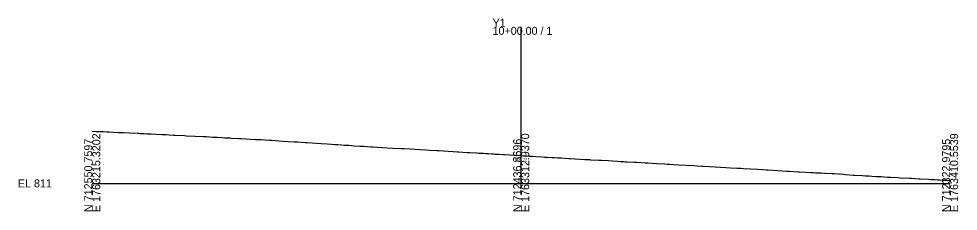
# Model space of a CAD drawing. Extents: x -26 to 1303, y -10 to 9524.
# Drawn here: x -25.7 to 302.8, y -9.7 to 57.5 of the extents above; entities that cross this region are included whole.
import ezdxf

# ---------------------------------------------------------------- set-up
doc = ezdxf.new("R2010")
doc.units = 0
for name, color, linetype in [('Default', 7, 'Continuous'), ('Exist Cross Section Cell', 7, 'Continuous'), ('Exist XS Center Line Elevation Label', 7, 'Continuous'), ('Exist XS Ground Line', 7, 'Continuous')]:
    doc.layers.add(name, color=color, linetype=linetype)

msp = doc.modelspace()

# ---------------------------------------------------------------- linework, layer by layer
at = {"layer": 'Exist Cross Section Cell'}
for p, q in [((150, 0), (150, 54.67)), ((0, 0), (150, 0)), ((150, 0), (300, 0))]:
    msp.add_line(p, q, dxfattribs=at)
at = {"layer": 'Exist XS Ground Line'}
msp.add_lwpolyline([(0, 18.22), (1.43, 18.18), (2.08, 18.16), (2.65, 18.14), (3.86, 18.08), (5.27, 18.01), (5.63, 18), (5.94, 17.99), (7.4, 17.92), (9.23, 17.82), (10.95, 17.75), (12.95, 17.66), (15.82, 17.53), (16.27, 17.51), (16.79, 17.48), (18.04, 17.41), (19.11, 17.35), (20.64, 17.28), (22.4, 17.19), (24.48, 17.09), (25.7, 17.03), (26.91, 16.97), (28.32, 16.9), (28.68, 16.88), (28.99, 16.86), (32.28, 16.7), (33, 16.66), (36, 16.52), (38.87, 16.39), (39.84, 16.33), (42.16, 16.2), (43.69, 16.1), (45.45, 16), (46.41, 15.96), (47.53, 15.9), (48.18, 15.86), (48.74, 15.84), (51.37, 15.7), (52.04, 15.66), (55.33, 15.46), (57.05, 15.38), (58.62, 15.3), (59.05, 15.28), (61.91, 15.12), (62.37, 15.08), (62.89, 15.06), (65.21, 14.92), (66.74, 14.8), (68.5, 14.68), (70.58, 14.57), (71.23, 14.53), (71.79, 14.5), (74.42, 14.31), (75.09, 14.26), (78.38, 14.02), (80.1, 13.9), (82.1, 13.8), (83.64, 13.7), (84.96, 13.6), (85.42, 13.57), (85.94, 13.54), (87.19, 13.46), (88.26, 13.4), (88.96, 13.36), (89.78, 13.3), (91.55, 13.17), (93.63, 13.04), (94.28, 13), (94.84, 12.97), (97.47, 12.81), (97.83, 12.78), (98.13, 12.76), (99.6, 12.69), (101.43, 12.56), (103.15, 12.48), (105.15, 12.34), (108.01, 12.2), (108.99, 12.14), (111.3, 12.02), (112.83, 11.94), (114.6, 11.85), (116.68, 11.73), (117.89, 11.66), (120.52, 11.5), (121.18, 11.46), (124.47, 11.26), (126.19, 11.17), (127.77, 11.06), (128.2, 11.03), (131.06, 10.85), (132.04, 10.79), (134.35, 10.65), (135.06, 10.61), (135.88, 10.56), (136.83, 10.52), (137.65, 10.46), (138.61, 10.4), (139.72, 10.32), (140.38, 10.28), (140.94, 10.26), (142.15, 10.21), (143.57, 10.11), (144.23, 10.06), (147.52, 9.87), (148.22, 9.83), (150, 9.72), (151.25, 9.64), (152.79, 9.56), (154.11, 9.47), (155.09, 9.41), (157.4, 9.25), (158.11, 9.2), (158.93, 9.15), (160.69, 9.07), (161.65, 9.02), (162.77, 8.94), (163.43, 8.91), (163.99, 8.88), (166.62, 8.73), (167.28, 8.68), (170.57, 8.5), (172.29, 8.39), (173.86, 8.31), (174.3, 8.29), (177.16, 8.12), (178.14, 8.08), (180.45, 7.95), (181.98, 7.87), (183.74, 7.76), (184.7, 7.7), (185.82, 7.63), (186.42, 7.59), (187.04, 7.56), (189.66, 7.42), (190.33, 7.38), (193.51, 7.18), (193.86, 7.15), (194.31, 7.13), (197.35, 6.96), (200.21, 6.79), (201.19, 6.74), (202.02, 6.7), (203.5, 6.61), (205.03, 6.53), (210.41, 6.23), (211.49, 6.17), (213.21, 6.08), (213.78, 6.04), (215.98, 5.92), (221.55, 5.59), (223.25, 5.49), (225.38, 5.36), (226.52, 5.29), (226.87, 5.27), (227.79, 5.23), (232.66, 4.97), (234.38, 4.85), (235.76, 4.77), (236.42, 4.73), (239.72, 4.55), (241.14, 4.42), (242.91, 4.32), (243.61, 4.28), (246.84, 4.08), (247.29, 4.06), (249.6, 3.94), (251.13, 3.84), (252.08, 3.79), (252.89, 3.75), (254.97, 3.65), (256.18, 3.58), (258.81, 3.45), (259.47, 3.42), (260.94, 3.32), (262.77, 3.18), (263.44, 3.12), (266.06, 2.9), (266.5, 2.87), (269.35, 2.72), (270.34, 2.68), (271.58, 2.62), (272.64, 2.55), (274.18, 2.46), (275.94, 2.36), (278.02, 2.23), (279.23, 2.16), (281.86, 2.03), (282.52, 1.99), (285.81, 1.83), (286.48, 1.79), (289.11, 1.63), (289.55, 1.61), (292.4, 1.44), (293.39, 1.39), (294.63, 1.33), (295.69, 1.27), (296.4, 1.24), (297.23, 1.19), (298.17, 1.14), (298.99, 1.09), (300, 1.03)], dxfattribs=at)

# ---------------------------------------------------------------- texts
at = {"layer": 'Default'}
msp.add_text('-', height=0.0001, dxfattribs=at).set_placement((0, 0))
at = {"layer": 'Exist Cross Section Cell'}
for s, p in [('Y1', (140, 54.67)), ('10+00.00 / 1', (140, 51.87)), ('EL 811', (-26, -1.4))]:
    msp.add_text(s, height=2.8, dxfattribs=at).set_placement(p)
for s, p in [('E 1763215.3202', (2.8, -10)), ('E 1763312.9370', (152.8, -10)), ('E 1763410.5539', (302.8, -10)), ('N 712550.7597', (0, -10)), ('N 712436.8696', (150, -10)), ('N 712322.9795', (300, -10))]:
    msp.add_text(s, height=2.8, rotation=90, dxfattribs=at).set_placement(p)
at = {"layer": 'Exist XS Center Line Elevation Label'}
msp.add_text('820.72', height=1, dxfattribs=at).set_placement((147.89, 7.72))

doc.saveas('drawing.dxf')
